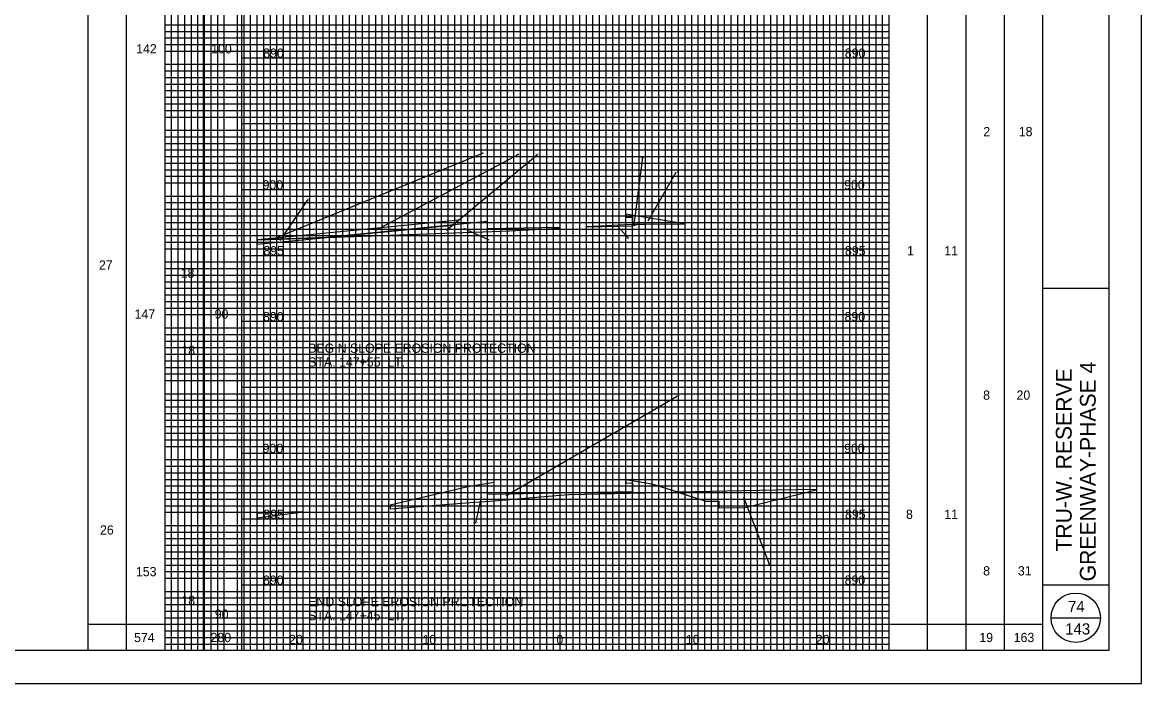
# Model space of a CAD drawing. Extents: x -73 to 160, y -2 to 1877.
# Drawn here: x 75 to 160, y -2.5 to 47.7 of the extents above; entities that cross this region are included whole.
import ezdxf

# ---------------------------------------------------------------- set-up
doc = ezdxf.new("R2010")
doc.units = 0
for name, color, linetype in [('DR_P_Flood_Boundary', 7, 'Continuous'), ('GK_Cells', 7, 'Continuous'), ('RD_X_Fence', 7, 'Continuous'), ('TX_X_5', 7, 'Continuous'), ('UT_P_Water_Cells', 7, 'Continuous'), ('XS_P_Pavt_Layers', 7, 'Continuous'), ('XS_P_Pavt_Surface', 7, 'Continuous'), ('XS_X_Ground_Line', 7, 'Continuous')]:
    doc.layers.add(name, color=color, linetype=linetype)

msp = doc.modelspace()

# ---------------------------------------------------------------- linework, layer by layer
at = {"layer": 'DR_P_Flood_Boundary'}
for p, q in [((95.832, 0), (95.832, 105)), ((100.832, 0), (100.832, 105)), ((105.832, 0), (105.832, 105)), ((110.832, 0), (110.832, 105)), ((115.832, 0), (115.832, 105)), ((120.832, 0), (120.832, 105)), ((125.832, 0), (125.832, 105)), ((130.832, 0), (130.832, 105)), ((135.832, 0), (135.832, 105)), ((91.665, 45), (140.832, 45)), ((91.665, 40), (140.832, 40)), ((91.665, 35), (140.832, 35)), ((91.665, 30), (140.832, 30)), ((91.665, 25), (140.832, 25)), ((91.665, 20), (140.832, 20)), ((91.665, 15), (140.832, 15)), ((91.665, 10), (140.832, 10)), ((91.665, 5), (140.832, 5))]:
    msp.add_line(p, q, dxfattribs=at)
at = {"layer": 'GK_Cells'}
for p, q in [((152.5, 0), (152.5, 105)), ((152.5, 27.5), (157.5, 27.5)), ((152.5, 5), (157.5, 5))]:
    msp.add_line(p, q, dxfattribs=at)
msp.add_lwpolyline([(0, 105), (157.5, 105), (157.5, 0), (0, 0)], close=True, dxfattribs=at)
at = {"layer": 'RD_X_Fence'}
for p, q in [((94.082, 31.257), (110.028, 37.781)), ((101.802, 31.897), (112.691, 37.682)), ((107.221, 31.914), (114.119, 37.648)), ((121.457, 32.314), (122.123, 37.433)), ((122.527, 32.632), (124.639, 36.322)), ((94.588, 31.125), (96.713, 34.246)), ((108.134, 32.673), (94.749, 31.36)), ((110.332, 32.559), (98.1, 31.359)), ((107.684, 32.299), (108.134, 32.673)), ((110.332, 32.011), (110.332, 32.559)), ((121.332, 32.345), (117.87, 32.162)), ((125.251, 32.401), (120.832, 33.138)), ((120.832, 32.888), (121.332, 32.898)), ((121.332, 32.898), (121.332, 32.345)), ((121.332, 32.231), (121.707, 32.365)), ((121.707, 32.365), (121.332, 32.345)), ((121.332, 32.231), (121.332, 32.345)), ((121.332, 32.345), (121.332, 32.231)), ((98.1, 31.359), (107.684, 32.299)), ((108.492, 32.053), (110.416, 31.182)), ((109.332, 31.757), (111.993, 31.851)), ((115.831, 32.121), (110.332, 32.011)), ((111.993, 31.851), (115.833, 32.054)), ((117.87, 32.162), (121.332, 32.231)), ((120.178, 32.246), (121.022, 31.308)), ((94.749, 31.36), (92.833, 31.172)), ((92.833, 30.842), (98.1, 31.359)), ((98.1, 31.359), (92.833, 31.172)), ((92.833, 31.172), (94.665, 31.237)), ((92.833, 31.172), (92.833, 30.842)), ((94.749, 31.36), (94.665, 31.237)), ((94.665, 31.237), (94.749, 31.36)), ((94.665, 31.237), (98.1, 31.359)), ((111.73, 11.785), (124.729, 19.31)), ((110.832, 12.771), (108.832, 12.437)), ((122.832, 12.637), (120.832, 12.971)), ((108.832, 12.437), (102.942, 11.031)), ((110.332, 12.511), (110.832, 12.521)), ((110.332, 11.844), (110.332, 12.511)), ((121.332, 12.064), (110.332, 11.844)), ((120.832, 12.721), (121.332, 12.731)), ((121.332, 12.731), (121.332, 12.064)), ((122.332, 11.97), (124.772, 12.022)), ((124.772, 12.022), (122.832, 12.637)), ((124.772, 12.022), (126.902, 11.346)), ((129.902, 10.87), (135.288, 12.217)), ((102.942, 10.77), (109.332, 11.258)), ((109.851, 11.661), (109.411, 9.704)), ((126.902, 11.346), (127.902, 11.346)), ((127.902, 11.346), (127.902, 10.846)), ((129.77, 11.66), (131.74, 6.526)), ((92.833, 10.091), (96.323, 10.547)), ((92.833, 10.421), (92.833, 10.091)), ((102.942, 11.031), (102.942, 10.77)), ((127.902, 10.846), (129.902, 10.87))]:
    msp.add_line(p, q, dxfattribs=at)
for points in [[(120.832, 33.138), (120.832, 33.034), (120.832, 32.888)], [(121.332, 32.345), (121.707, 32.365), (122.332, 32.371), (125.251, 32.401)], [(98.1, 31.359), (109.16, 31.751), (109.332, 31.757)], [(115.833, 32.054), (115.831, 32.121)], [(110.832, 12.521), (110.832, 12.667), (110.832, 12.771)], [(120.832, 12.971), (120.832, 12.867), (120.832, 12.721)], [(115.833, 11.789), (116.536, 11.847), (122.332, 11.97)], [(135.288, 12.219), (132.232, 12.18), (124.772, 12.022)], [(135.288, 12.217), (135.288, 12.219)], [(109.332, 11.258), (109.768, 11.294), (110.822, 11.38), (115.833, 11.789)], [(96.323, 10.547), (94.22, 10.492), (92.833, 10.421)]]:
    msp.add_lwpolyline(points, dxfattribs=at)
at = {"layer": 'TX_X_5'}
msp.add_lwpolyline([(-10, -2.5), (160, -2.5), (160, 107.5), (-10, 107.5)], close=True, dxfattribs=at)
at = {"layer": 'UT_P_Water_Cells'}
for p, q in [((86.332, 0), (86.332, 105)), ((86.832, 0), (86.832, 105)), ((87.332, 0), (87.332, 105)), ((87.832, 0), (87.832, 105)), ((88.332, 0), (88.332, 105)), ((88.832, 0), (88.832, 105)), ((89.332, 0), (89.332, 105)), ((89.832, 0), (89.832, 105)), ((90.332, 0), (90.332, 105)), ((91.332, 0), (91.332, 105)), ((91.832, 0), (91.832, 105)), ((92.332, 0), (92.332, 105)), ((92.832, 0), (92.832, 105)), ((93.332, 0), (93.332, 105)), ((93.832, 0), (93.832, 105)), ((94.332, 0), (94.332, 105)), ((94.832, 0), (94.832, 105)), ((95.332, 0), (95.332, 105)), ((96.332, 0), (96.332, 105)), ((96.832, 0), (96.832, 105)), ((97.332, 0), (97.332, 105)), ((97.832, 0), (97.832, 105)), ((98.332, 0), (98.332, 105)), ((98.832, 0), (98.832, 105)), ((99.332, 0), (99.332, 105)), ((99.832, 0), (99.832, 105)), ((100.332, 0), (100.332, 105)), ((101.332, 0), (101.332, 105)), ((101.832, 0), (101.832, 105)), ((102.332, 0), (102.332, 105)), ((102.832, 0), (102.832, 105)), ((103.332, 0), (103.332, 105)), ((103.832, 0), (103.832, 105)), ((104.332, 0), (104.332, 105)), ((104.832, 0), (104.832, 105)), ((105.332, 0), (105.332, 105)), ((106.332, 0), (106.332, 105)), ((106.832, 0), (106.832, 105)), ((107.332, 0), (107.332, 105)), ((107.832, 0), (107.832, 105)), ((108.332, 0), (108.332, 105)), ((108.832, 0), (108.832, 105)), ((109.332, 0), (109.332, 105)), ((109.832, 0), (109.832, 105)), ((110.332, 0), (110.332, 105)), ((111.332, 0), (111.332, 105)), ((111.832, 0), (111.832, 105)), ((112.332, 0), (112.332, 105)), ((112.832, 0), (112.832, 105)), ((113.332, 0), (113.332, 105)), ((113.832, 0), (113.832, 105)), ((114.332, 0), (114.332, 105)), ((114.832, 0), (114.832, 105)), ((115.332, 0), (115.332, 105)), ((116.332, 0), (116.332, 105)), ((116.832, 0), (116.832, 105)), ((117.332, 0), (117.332, 105)), ((117.832, 0), (117.832, 105)), ((118.332, 0), (118.332, 105)), ((118.832, 0), (118.832, 105)), ((119.332, 0), (119.332, 105)), ((119.832, 0), (119.832, 105)), ((120.332, 0), (120.332, 105)), ((121.332, 0), (121.332, 105)), ((121.832, 0), (121.832, 105)), ((122.332, 0), (122.332, 105)), ((122.832, 0), (122.832, 105)), ((123.332, 0), (123.332, 105)), ((123.832, 0), (123.832, 105)), ((124.332, 0), (124.332, 105)), ((124.832, 0), (124.832, 105)), ((125.332, 0), (125.332, 105)), ((126.332, 0), (126.332, 105)), ((126.832, 0), (126.832, 105)), ((127.332, 0), (127.332, 105)), ((127.832, 0), (127.832, 105)), ((128.332, 0), (128.332, 105)), ((128.832, 0), (128.832, 105)), ((129.332, 0), (129.332, 105)), ((129.832, 0), (129.832, 105)), ((130.332, 0), (130.332, 105)), ((131.332, 0), (131.332, 105)), ((131.832, 0), (131.832, 105)), ((132.332, 0), (132.332, 105)), ((132.832, 0), (132.832, 105)), ((133.332, 0), (133.332, 105)), ((133.832, 0), (133.832, 105)), ((134.332, 0), (134.332, 105)), ((134.832, 0), (134.832, 105)), ((135.332, 0), (135.332, 105)), ((136.332, 0), (136.332, 105)), ((136.832, 0), (136.832, 105)), ((137.332, 0), (137.332, 105)), ((137.832, 0), (137.832, 105)), ((138.332, 0), (138.332, 105)), ((138.832, 0), (138.832, 105)), ((139.332, 0), (139.332, 105)), ((139.832, 0), (139.832, 105)), ((140.332, 0), (140.332, 105)), ((85.832, 47.5), (140.832, 47.5)), ((85.832, 47), (140.832, 47)), ((85.832, 46.5), (140.832, 46.5)), ((85.832, 46), (140.832, 46)), ((85.832, 45.5), (140.832, 45.5)), ((85.832, 44.5), (140.832, 44.5)), ((85.832, 44), (140.832, 44)), ((85.832, 43.5), (140.832, 43.5)), ((85.832, 43), (140.832, 43)), ((85.832, 42.5), (140.832, 42.5)), ((85.832, 42), (140.832, 42)), ((85.832, 41.5), (140.832, 41.5)), ((85.832, 41), (140.832, 41)), ((85.832, 40.5), (140.832, 40.5)), ((85.832, 39.5), (140.832, 39.5)), ((85.832, 39), (140.832, 39)), ((85.832, 38.5), (140.832, 38.5)), ((85.832, 38), (140.832, 38)), ((85.832, 37.5), (140.832, 37.5)), ((85.832, 37), (140.832, 37)), ((85.832, 36.5), (140.832, 36.5)), ((85.832, 36), (140.832, 36)), ((85.832, 35.5), (140.832, 35.5)), ((85.832, 34.5), (140.832, 34.5)), ((85.832, 34), (140.832, 34)), ((85.832, 33.5), (140.832, 33.5)), ((85.832, 33), (140.832, 33)), ((85.832, 32.5), (140.832, 32.5)), ((85.832, 32), (140.832, 32)), ((85.832, 31.5), (140.832, 31.5)), ((85.832, 31), (140.832, 31)), ((85.832, 30.5), (140.832, 30.5)), ((85.832, 29.5), (140.832, 29.5)), ((85.832, 29), (140.832, 29)), ((85.832, 28.5), (140.832, 28.5)), ((85.832, 28), (140.832, 28)), ((85.832, 27.5), (140.832, 27.5)), ((85.832, 27), (140.832, 27)), ((85.832, 26.5), (140.832, 26.5)), ((85.832, 26), (140.832, 26)), ((85.832, 25.5), (140.832, 25.5)), ((85.832, 24.5), (140.832, 24.5)), ((85.832, 24), (140.832, 24)), ((85.832, 23.5), (140.832, 23.5)), ((85.832, 23), (140.832, 23)), ((85.832, 22.5), (140.832, 22.5)), ((85.832, 22), (140.832, 22)), ((85.832, 21.5), (140.832, 21.5)), ((85.832, 21), (140.832, 21)), ((85.832, 20.5), (140.832, 20.5)), ((85.832, 19.5), (140.832, 19.5)), ((85.832, 19), (140.832, 19)), ((85.832, 18.5), (140.832, 18.5)), ((85.832, 18), (140.832, 18)), ((85.832, 17.5), (140.832, 17.5)), ((85.832, 17), (140.832, 17)), ((85.832, 16.5), (140.832, 16.5)), ((85.832, 16), (140.832, 16)), ((85.832, 15.5), (140.832, 15.5)), ((85.832, 14.5), (140.832, 14.5)), ((85.832, 14), (140.832, 14)), ((85.832, 13.5), (140.832, 13.5)), ((85.832, 13), (140.832, 13)), ((85.832, 12.5), (140.832, 12.5)), ((85.832, 12), (140.832, 12)), ((85.832, 11.5), (140.832, 11.5)), ((85.832, 11), (140.832, 11)), ((85.832, 10.5), (140.832, 10.5)), ((85.832, 9.5), (140.832, 9.5)), ((85.832, 9), (140.832, 9)), ((85.832, 8.5), (140.832, 8.5)), ((85.832, 8), (140.832, 8)), ((85.832, 7.5), (140.832, 7.5)), ((85.832, 7), (140.832, 7)), ((85.832, 6.5), (140.832, 6.5)), ((85.832, 6), (140.832, 6)), ((85.832, 5.5), (140.832, 5.5)), ((85.832, 4.5), (140.832, 4.5)), ((85.832, 4), (140.832, 4)), ((85.832, 3.5), (140.832, 3.5)), ((85.832, 3), (140.832, 3)), ((85.832, 2.5), (140.832, 2.5)), ((85.832, 2), (140.832, 2)), ((85.832, 1.5), (140.832, 1.5)), ((85.832, 1), (140.832, 1)), ((85.832, 0.5), (140.832, 0.5))]:
    msp.add_line(p, q, dxfattribs=at)
at = {"layer": 'XS_X_Ground_Line'}
for p, q in [((80, 0), (80, 105)), ((85.832, 0), (85.832, 105)), ((85.832, 0), (85.832, 105)), ((91.665, 0), (91.665, 105)), ((140.832, 0), (140.832, 105)), ((146.667, 0), (146.667, 105)), ((82.916, 0), (82.916, 103.75)), ((143.75, 0), (143.75, 103.75)), ((149.583, 0), (149.583, 103.75)), ((88.749, 0), (88.749, 101.667)), ((155, 16.458), (155, 16.458)), ((155, 2.925), (155, 2.925)), ((80, 2), (91.665, 2)), ((140.832, 2), (152.5, 2)), ((153.125, 2.5), (156.875, 2.5)), ((81.458, 1.03), (81.458, 1.03)), ((84.374, 1.03), (84.374, 1.03)), ((142.291, 1), (142.291, 1)), ((145.209, 1), (145.209, 1)), ((148.125, 1), (148.125, 1)), ((151.042, 1), (151.042, 1)), ((155, 1.225), (155, 1.225))]:
    msp.add_line(p, q, dxfattribs=at)
msp.add_circle((155, 2.5), 1.875, dxfattribs=at)

# ---------------------------------------------------------------- texts
at = {"layer": 'RD_X_Fence'}
for s, p in [('0.1', (109.886, 37.711)), ('4.0', (112.529, 37.612)), ('5.5', (113.96, 37.578)), ('0.0', (121.955, 37.363)), ('1.5', (124.508, 36.252)), ('0.9', (96.547, 34.176)), ('0.2', (120.87, 31.238)), ('10.8', (124.532, 19.24)), ('14.2', (109.232, 9.634)), ('7.4', (131.584, 6.456))]:
    msp.add_text(s, height=0.14, dxfattribs=at).set_placement(p)
at = {"layer": 'XS_P_Pavt_Layers'}
for s, p in [('74', (154.411, 2.925)), ('143', (154.197, 1.225))]:
    msp.add_text(s, height=0.85, dxfattribs=at).set_placement(p)
at = {"layer": 'XS_P_Pavt_Surface'}
for s, p in [('142', (83.641, 45.326)), ('100', (89.339, 45.326)), ('890', (93.292, 45)), ('890', (137.46, 45)), ('2', (147.977, 39.044)), ('18', (150.67, 39.044)), ('900', (93.243, 35)), ('900', (137.41, 35)), ('895', (93.303, 30)), ('895', (137.471, 30)), ('1', (142.182, 30)), ('11', (145.013, 30)), ('27', (80.814, 28.919)), ('18', (87.021, 28.3)), ('147', (83.525, 25.201)), ('90', (89.606, 25.201)), ('890', (93.276, 25)), ('890', (137.443, 25)), ('18', (87.074, 22.439)), ('BEGIN SLOPE EROSION PROTECTION', (96.708, 22.607)), ('STA. 147+55, LT.', (96.708, 21.557)), ('8', (147.963, 19.044)), ('20', (150.499, 19.044)), ('900', (93.243, 15)), ('900', (137.41, 15)), ('895', (93.303, 10)), ('895', (137.471, 10)), ('8', (142.105, 10)), ('11', (145.013, 10)), ('26', (80.896, 8.812)), ('153', (83.624, 5.649)), ('8', (147.963, 5.708)), ('31', (150.603, 5.708)), ('890', (93.276, 5)), ('890', (137.443, 5)), ('18', (87.074, 3.466)), ('END SLOPE EROSION PROTECTION', (96.708, 3.363)), ('90', (89.614, 2.423)), ('STA. 147+45, LT.', (96.708, 2.313)), ('574', (83.482, 0.65)), ('280', (89.293, 0.65)), ('20', (95.257, 0.5)), ('10', (105.389, 0.5)), ('0', (115.554, 0.5)), ('0', (115.554, 0.5)), ('10', (125.389, 0.5)), ('20', (135.257, 0.5)), ('19', (147.676, 0.65)), ('163', (150.287, 0.65))]:
    msp.add_text(s, height=0.7, dxfattribs=at).set_placement(p)
for s, p in [('TRU-W. RESERVE', (154.688, 7.519)), ('GREENWAY-PHASE 4', (156.512, 5.261))]:
    msp.add_text(s, height=1.2, rotation=90, dxfattribs=at).set_placement(p)
at = {"layer": 'XS_X_Ground_Line'}
msp.add_text('143', height=0.85, dxfattribs=at).set_placement((154.197, 1.225))

doc.saveas('drawing.dxf')
